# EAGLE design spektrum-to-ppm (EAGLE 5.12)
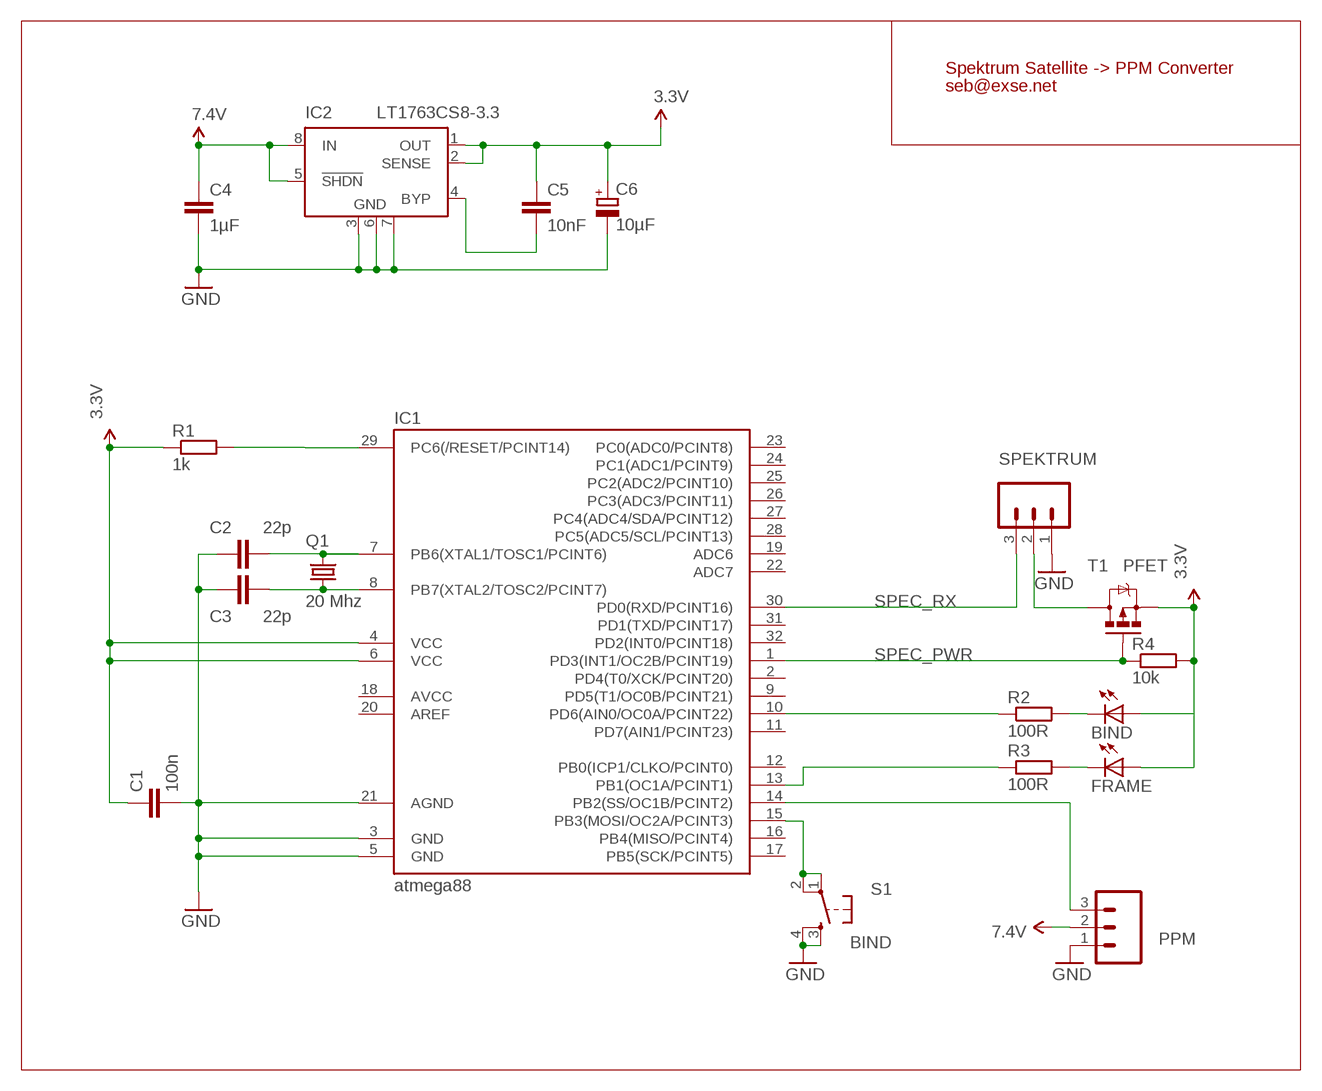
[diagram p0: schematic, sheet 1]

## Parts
BIND  LEDCHIPLED_0805  [CHIPLED_0805]
C1  100n  CAP0805  [0805]
C2  22p  C-EUC0402  [C0402]
C3  22p  C-EUC0402  [C0402]
C4  1µF  CAP0805  [0805]
C5  10nF  C-EUC0402  [C0402]
C6  10µF  CPOL-EUSMCC  [SMC_C]
FRAME  LEDCHIPLED_0805  [CHIPLED_0805]
IC1  atmega88  MEGA48/88/168-AU  [TQFP32-08]
IC2  LT1763CS8-3.3  [SOIC8]
PPM  M03LONGPADS  [1X03_LONGPADS]
Q1  20 Mhz  X22-OSCILLATOR  [X22]
R1  1k  R-EU_R0402  [R0402]
R2  100R  R-EU_R0402  [R0402]
R3  100R  R-EU_R0402  [R0402]
R4  10k  R-EU_R0402  [R0402]
S1  BIND  TAC_SWITCHSMD  [TACTILE_SWITCH_SMD]
SPEKTRUM  M03LONGPADS  [1X03_LONGPADS]
T1  PFET  MOSFET-PCHANNEL  [SOT23]

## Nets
3.3V: BIND.A C1.1 C5.1 C6.+ FRAME.A IC1.4(VCC) IC1.6(VCC) IC2.1(OUT) IC2.2(SENSE) R1.1 T1.2(S)
5V: C4.1 IC2.5(!SHDN) IC2.8(IN) PPM.2 ; supply symbol labelled 7.4V
GND: C1.2 C2.1 C3.1 C4.2 C6.- IC1.3(GND) IC1.5(GND) IC1.21(AGND) IC2.3(GND) IC2.6(GND) IC2.7(GND) PPM.1 S1.3 S1.4 SPEKTRUM.1
N$1: C5.2 IC2.4(BYP)
N$2: IC1.15(PB3(MOSI/OC2A/PCINT3)) S1.1 S1.2
N$3: SPEKTRUM.2 T1.3(D)
N$4: IC1.14(PB2(SS/OC1B/PCINT2)) PPM.3
N$5: R4.2
N$6: BIND.C R2.2
N$8: IC1.29(PC6(/RESET/PCINT14)) R1.2
N$9: C3.2 IC1.8(PB7(XTAL2/TOSC2/PCINT7)) Q1.1
N$10: C2.2 IC1.7(PB6(XTAL1/TOSC1/PCINT6)) Q1.3
N$11: IC1.10(PD6(AIN0/OC0A/PCINT22)) R2.1
N$14: FRAME.C R3.2
N$15: IC1.13(PB1(OC1A/PCINT1)) R3.1
SPEC_PWR: IC1.1(PD3(INT1/OC2B/PCINT19)) R4.1 T1.1(G)
SPEC_RX: IC1.30(PD0(RXD/PCINT16)) SPEKTRUM.3
Unconnected: IC1.2(PD4(T0/XCK/PCINT20)) IC1.9(PD5(T1/OC0B/PCINT21)) IC1.11(PD7(AIN1/PCINT23)) IC1.12(PB0(ICP1/CLKO/PCINT0)) IC1.16(PB4(MISO/PCINT4)) IC1.17(PB5(SCK/PCINT5)) IC1.18(AVCC) IC1.19(ADC6) IC1.20(AREF) IC1.22(ADC7) IC1.23(PC0(ADC0/PCINT8)) IC1.24(PC1(ADC1/PCINT9)) IC1.25(PC2(ADC2/PCINT10)) IC1.26(PC3(ADC3/PCINT11)) IC1.27(PC4(ADC4/SDA/PCINT12)) IC1.28(PC5(ADC5/SCL/PCINT13)) IC1.31(PD1(TXD/PCINT17)) IC1.32(PD2(INT0/PCINT18))

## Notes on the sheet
- Spektrum Satellite -> PPM Converter
- seb@exse.net

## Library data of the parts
BIND FRAME = led:LED: LED
C1 C4 = SparkFun:CAP: Capacitor
C2 C3 C5 = rcl:C-EU: CAPACITOR, European symbol
C6 = resistor:CPOL-EU: POLARIZED CAPACITOR, European symbol
IC1 = avr-4:MEGA48/88/168
IC2 = linear-technology:LT1763CS8: 500mA, Low Noise, LDO Micropower Regulators Source: http://cds.linear.com/docs/Datasheet/1763ff.pdf
PPM SPEKTRUM = SparkFun:M03: Header 3 Standard 3-pin 0.1" header. Use with straight break away headers (SKU : PRT-00116), right angle break away headers (PRT-00553), swiss pins (PRT-00743), machine pins (PRT-00117), and female headers (PRT-00115). Molex polarized connector foot print use with SKU : PRT-08232 with associated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
Q1 = seb:X22-OSCILLATOR
R1-R4 = rcl:R-EU_: RESISTOR, European symbol
S1 = SparkFun:TAC_SWITCH: Momentary Switch Button commonly used for reset or general input. Spark Fun Electronics SKU : COM-00097
T1 = SparkFun:MOSFET-PCHANNEL

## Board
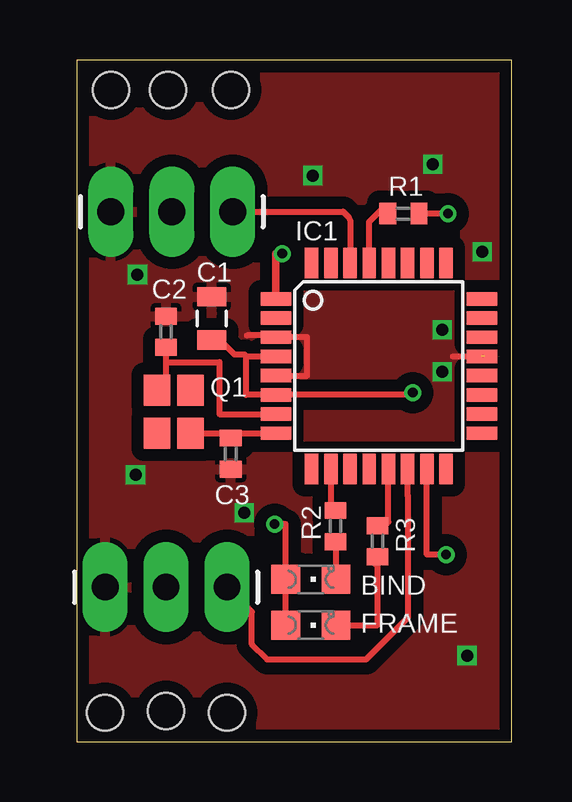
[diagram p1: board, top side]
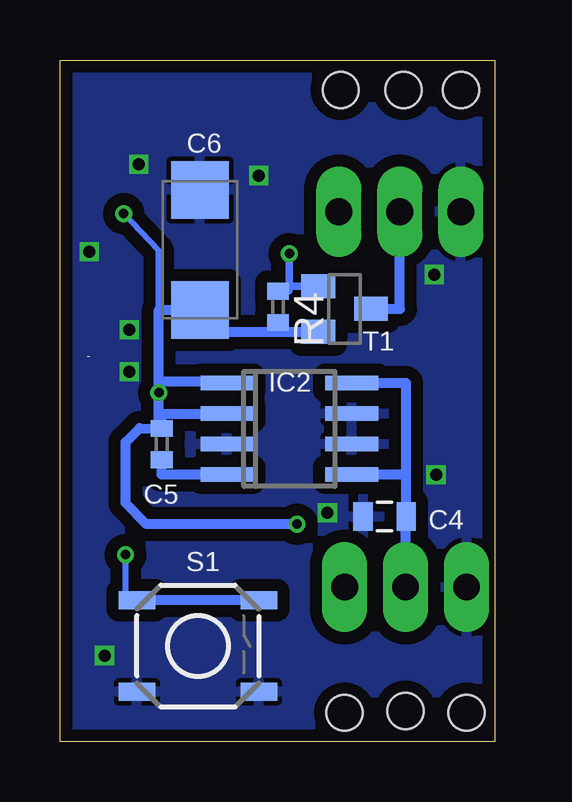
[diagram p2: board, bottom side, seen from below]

Size 18.12 x 28.4 mm. Coordinates in mm from the lower left corner, seen from the top.
Outline: 0,0 18.12,0 18.12,28.4 0,28.4 0,0
Copper layers (1*16): Top 0.035mm / dielectric 1.5mm / Bottom 0.035mm
Design rules "PCB-POOL Standard *": minimum track width 0.15mm, minimum drill 0.3mm, track to track 0.15mm, track to pad 0.15mm, pad to pad 0.15mm, via to via 0.15mm, smd to smd 0.15mm, copper to edge 0.1mm, drill to drill 0.2mm, minimum pad ring 0.2mm, minimum via ring 0.15mm, stop-mask expansion 0.075mm, vias tented up to drill 30mil, thermal gap 0.2mm
Holes 1.5 mm at 1.18,1.2 3.72,1.28 6.26,1.2 1.42,27.16 3.8,27.16 6.42,27.16

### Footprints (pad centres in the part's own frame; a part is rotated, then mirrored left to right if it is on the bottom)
CHIPLED_0805 = smd 1.2 x 1.2: A 0,-1.05; C 0,1.05
0805 = smd 0.8 x 1.2: 1 -0.9,0; 2 0.9,0
C0402 = smd 0.7 x 0.9: 1 -0.65,0; 2 0.65,0
SMC_C = smd 2.4 x 2.4: + -2.5,0; - 2.5,0
TQFP32-08 = smd 1.27 x 0.559: 1 -4.293,2.8; 2 -4.293,2; 3 -4.293,1.2; 4 -4.293,0.4; 5 -4.293,-0.4; 6 -4.293,-1.2; 7 -4.293,-2; 8 -4.293,-2.8; 17 4.293,-2.8; 18 4.293,-2; 19 4.293,-1.2; 20 4.293,-0.4; 21 4.293,0.4; 22 4.293,1.2; 23 4.293,2; 24 4.293,2.8 | smd 0.559 x 1.27: 9 -2.8,-4.293; 10 -2,-4.293; 11 -1.2,-4.293; 12 -0.4,-4.293; 13 0.4,-4.293; 14 1.2,-4.293; 15 2,-4.293; 16 2.8,-4.293; 25 2.8,4.293; 26 2,4.293; 27 1.2,4.293; 28 0.4,4.293; 29 -0.4,4.293; 30 -1.2,4.293; 31 -2,4.293; 32 -2.8,4.293
SOIC8 = smd 0.6 x 2.2: 1 -1.905,-2.6; 2 -0.635,-2.6; 3 0.635,-2.6; 4 1.905,-2.6; 5 1.905,2.6; 6 0.635,2.6; 7 -0.635,2.6; 8 -1.905,2.6
1X03_LONGPADS = drill 1.118 pad 1.88 long: 1 0,0; 2 2.54,0; 3 5.08,0
X22 = smd 1.3 x 1.1: 1 0.9,0.7; 2 -0.9,0.7; 3 -0.9,-0.7; 4 0.9,-0.7
R0402 = smd 0.7 x 0.9: 1 -0.65,0; 2 0.65,0
TACTILE_SWITCH_SMD = smd 1.524 x 0.762: 1 -2.54,1.905; 2 2.54,1.905; 3 -2.54,-1.905; 4 2.54,-1.905
SOT23 = smd 1 x 1.4: 1 -0.95,-1.1; 2 0.95,-1.1; 3 0,1.1

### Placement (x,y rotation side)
BIND  9.75,6.76 270 top
C1  5.62,17.63 90 top
C2  3.72,17.08 270 top
C3  6.41,12 90 top
C4  4.59,9.38 180 bottom
C5  13.88,12.39 270 bottom
C6  12.29,20.49 90 bottom
FRAME  9.75,4.85 270 top
IC1  12.58,15.65 0 top
IC2  8.56,13.03 270 bottom
PPM  1.18,6.44 0 top
Q1  4.04,13.74 270 top
R1  13.61,22 180 top
R2  10.78,8.98 270 top
R3  12.53,8.35 270 top
R4  9.04,18.11 270 bottom
S1  12.37,3.98 0 bottom
SPEKTRUM  1.42,22.08 0 top
T1  6.26,18.03 270 bottom

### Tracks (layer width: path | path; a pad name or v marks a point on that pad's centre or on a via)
3.3V  (via drill 0.4)
  Top 0.254: 7.05,16.05 IC1.4 | 7.05,16.05 7.05,14.45 IC1.6 14,14.45 v14,14.54 | R1.1 14.74,22 v15.47,22 | 7.05,16.05 6.98,16.12 6.58,16.12 5.97,16.73 C1.1 | v8.24,9.06 8.7,9.06 BIND.A FRAME.A
  Bottom 0.254: v15.47,22 14,20.45 14,17.71
  Bottom 0.406: 13.88,13.66 C5.1 14.8,13.06 15.39,12.47 15.39,9.93 14.51,9.06 v8.24,9.06 | 13.88,13.66 IC2.2 | 14,15.01 v14,14.54 14,13.27 13.88,13.66 | IC2.1 11.16,15.01 14,15.01 | 14,15.01 14,17.71 14,17.99 C6.+ 12.29,17.08 8.88,17.08 | 8.88,17.08 T1.2 | 8.88,17.08 8.88,17.46
5V
  Bottom 0.406: PPM.2 3.72,9.35 C4.1 3.69,11.12 | 3.69,11.12 IC2.5 | IC2.8 3.69,14.93 3.69,11.12
GND  (via drill 0.5)  (1 unrouted)
  Top 0.254: IC1.5 9.59,15.25 9.59,16.85 IC1.3 8.24,16.9 8.24,16.93 | 8.24,16.93 8.4,16.93 | 8.24,16.93 7.1,16.93 | 15.67,16.05 16.97,16.05
  Top 0.406: PPM.1 1.18,7.47
  other vias: 2.53,19.46 15.23,15.41 15.23,17.16 16.9,20.41 9.83,23.59 14.83,24.06 2.45,11.12 6.97,9.54 16.26,3.58
  pour Bottom (isolate 0.508): 0.07,28.51 17.85,28.51 17.85,-0.23 0.07,-0.23
  pour Top (isolate 0.508): -0.09,28.51 17.69,28.51 17.69,-0.23 -0.09,-0.23
N$1
  Bottom 0.406: C5.2 13.88,11.12 IC2.4
N$2  (via drill 0.4)
  Top 0.254: v15.39,7.79 14.58,7.79 IC1.15
  Bottom 0.254: S1.1 15.39,5.89 v15.39,7.79
  Bottom 0.406: S1.2 S1.1
N$3
  Bottom 0.406: T1.3 3.96,18.03 SPEKTRUM.2
N$4
  Top 0.254: IC1.14 13.78,10.25 13.8,10.25 13.8,6.12 13.8,5.17 12.05,3.42 7.93,3.42 7.29,4.06 7.29,5.41 PPM.3
N$6
  Top 0.254: BIND.C 10.78,6.76 R2.2
N$8
  Top 0.254: R1.2 12.77,22.24 12.18,21.65 IC1.29
N$9
  Top 0.254: 6.65,12.85 C3.2 | 6.65,12.85 IC1.8 | Q1.1 5.21,12.85 6.65,12.85
N$10
  Top 0.254: Q1.3 3.72,14.17 3.72,15.81 | IC1.7 5.94,13.65 5.94,15.81 3.72,15.81 | 3.72,15.81 C2.2
N$11
  Top 0.254: R2.1 10.58,9.63 IC1.10
N$14
  Top 0.254: 12.42,7.39 R3.2 12.53,4.85 FRAME.C
N$15
  Top 0.254: R3.1 12.98,9.14 IC1.13
SPEC_PWR  (via drill 0.4)
  Top 0.305: v8.56,20.33 8.29,20.33 IC1.1
  Bottom 0.254: R4.1 8.56,18.76 8.56,19.22
  Bottom 0.305: T1.1 8.56,18.98 8.56,19.22 v8.56,20.33
SPEC_RX
  Top 0.254: SPEKTRUM.3 11.1,22.08 11.34,21.84 11.38,21.73 IC1.30

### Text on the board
tStop: Spektrum | seb@exse.net | PPM
bStop: - | + | s | - | + | s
